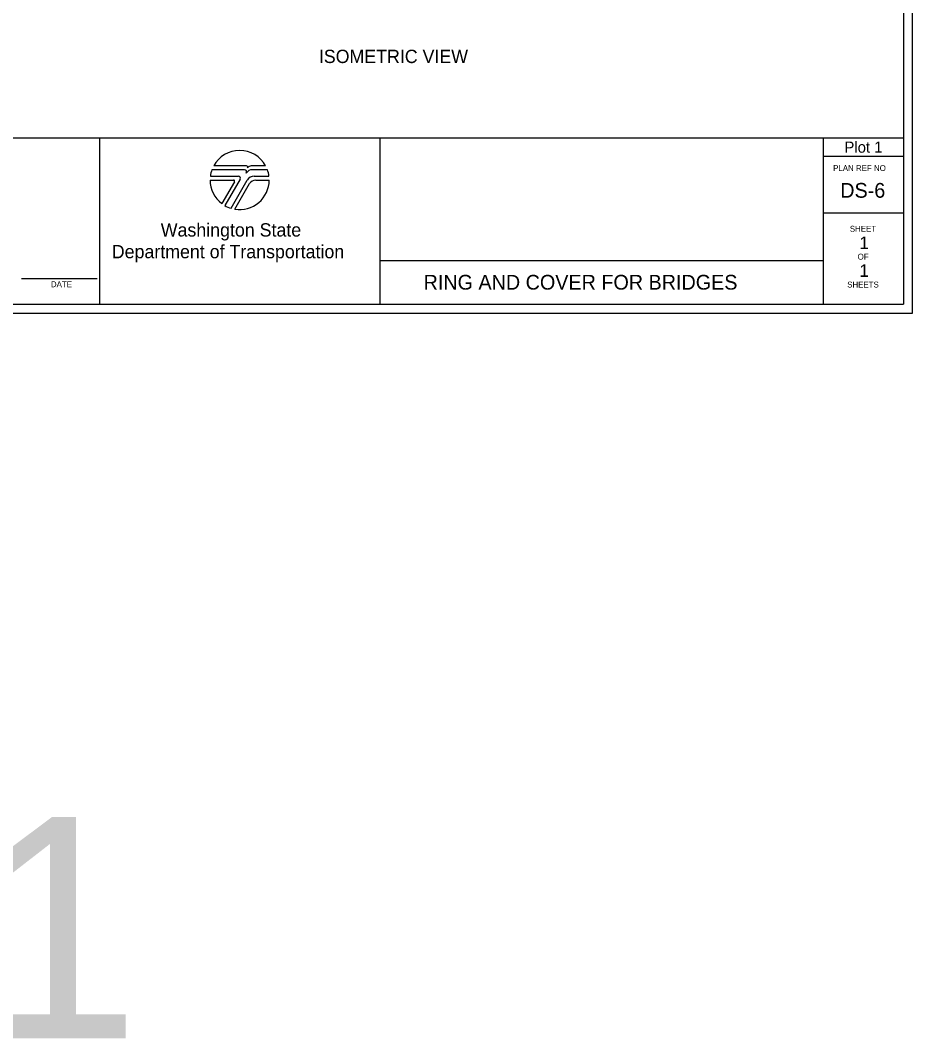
# Model space of a CAD drawing. Extents: x 99988 to 100172, y 99995 to 100047.
# Drawn here: x 100009.77 to 100015.81, y 99995.01 to 100001.92 of the extents above; entities that cross this region are included whole.
import ezdxf

# ---------------------------------------------------------------- set-up
doc = ezdxf.new("R2010")
doc.units = 0
for name, color, linetype in [('Level 10', 7, 'Continuous'), ('SH_GI_PlotLimits', 7, 'Continuous'), ('SH_GI_SheetBorder', 7, 'Continuous'), ('SH_GI_SheetLocationText', 7, 'Continuous'), ('SH_GI_SheetTextInCells', 7, 'Continuous'), ('SH_GI_TitleBlockText', 7, 'Continuous'), ('SH_GI_WSDOTLogo', 7, 'Continuous')]:
    doc.layers.add(name, color=color, linetype=linetype)

msp = doc.modelspace()

# ---------------------------------------------------------------- linework, layer by layer
at = {"layer": 'SH_GI_PlotLimits'}
msp.add_lwpolyline([(99999.3125, 99999.9375), (100015.8125, 99999.9375), (100015.8125, 100010.4375), (99999.3125, 100010.4375)], close=True, dxfattribs=at)
at = {"layer": 'SH_GI_SheetBorder'}
for p, q in [((100015.75, 100010.375), (100015.75, 100000)), ((100000, 100001.1259), (100015.75, 100001.1259)), ((100010.3089, 100001.1259), (100010.3089, 100000)), ((100012.2055, 100001.1259), (100012.2055, 100000)), ((100015.2079, 100001.1259), (100015.2079, 100000)), ((100015.2079, 100001.0008), (100015.75, 100001.0008)), ((100015.2079, 100000.6176), (100015.75, 100000.6176)), ((100012.2055, 100000.2955), (100015.2079, 100000.2955)), ((100009.7797, 100000.1733), (100010.2914, 100000.1733)), ((100000, 100000), (100015.75, 100000))]:
    msp.add_line(p, q, dxfattribs=at)
at = {"layer": 'SH_GI_WSDOTLogo'}
for p, q in [((100011.2894, 100000.9094), (100011.0697, 100000.9094)), ((100011.303, 100000.9354), (100011.0815, 100000.9354)), ((100011.433, 100000.9354), (100011.3351, 100000.9354)), ((100011.343, 100000.9094), (100011.3429, 100000.9094)), ((100011.4448, 100000.9094), (100011.343, 100000.9094)), ((100011.0572, 100000.84), (100011.2148, 100000.84)), ((100011.059, 100000.8661), (100011.2496, 100000.8661)), ((100011.222, 100000.8277), (100011.1364, 100000.6807)), ((100011.261, 100000.8464), (100011.1567, 100000.6672)), ((100011.1989, 100000.6487), (100011.3089, 100000.839)), ((100011.2244, 100000.6428), (100011.3242, 100000.8156)), ((100011.3558, 100000.8661), (100011.4555, 100000.8661)), ((100011.3655, 100000.8394), (100011.4572, 100000.8394))]:
    msp.add_line(p, q, dxfattribs=at)
for centre, radius, start, end in [((100011.2572, 100000.84), 0.2, 28.47865, 151.53204), ((100011.2572, 100000.84), 0.2, 159.69598, 172.50569), ((100011.2894, 100000.8946), 0.0148, 327.8418, 89.99855), ((100011.3429, 100000.861), 0.0484, 89.99529, 147.82376), ((100011.303, 100000.9263), 0.00903, 329.87418, 90.00328), ((100011.3352, 100000.9066), 0.0287, 90.00721, 148.16763), ((100011.2572, 100000.84), 0.2, 7.49431, 20.29406), ((100011.2572, 100000.84), 0.2, 179.99864, 232.84327), ((100011.2149, 100000.8318), 0.0082, 329.74356, 90), ((100011.2572, 100000.84), 0.2, 260.54554, 359.80857), ((100011.2497, 100000.853), 0.0131, 329.76834, 90), ((100011.3558, 100000.8119), 0.0542, 90, 149.99738), ((100011.3654, 100000.7918), 0.0476, 90, 150.05432), ((100011.2572, 100000.84), 0.2, 239.79292, 253.0448)]:
    msp.add_arc(centre, radius, start, end, dxfattribs=at)

# ---------------------------------------------------------------- texts
at = {"layer": 'Level 10'}
msp.add_text('ISOMETRIC VIEW', height=0.09, dxfattribs=at).set_placement((100011.7934, 100001.6322))
at = {"layer": 'SH_GI_SheetBorder'}
msp.add_text('PLAN REF NO', height=0.040032, dxfattribs=at).set_placement((100015.2747, 100000.9008))
at = {"layer": 'SH_GI_SheetLocationText'}
for height, p in [(0.075, (100015.3518, 100001.025)), (1.5, (100005.4547, 99995.0267))]:
    msp.add_text('Plot 1', height=height, dxfattribs=at).set_placement(p)
at = {"layer": 'SH_GI_SheetTextInCells'}
for s, height, p in [('Washington State', 0.090072, (100010.7229, 100000.4571)), ('SHEET', 0.04003, (100015.3877, 100000.4896)), ('Department of Transportation', 0.090072, (100010.3916, 100000.3101)), ('OF', 0.04003, (100015.4406, 100000.3008)), ('DATE', 0.04003, (100009.9794, 100000.1141)), ('SHEETS', 0.04003, (100015.3698, 100000.112))]:
    msp.add_text(s, height=height, dxfattribs=at).set_placement(p)
at = {"layer": 'SH_GI_TitleBlockText'}
for s, height, p in [('DS-6', 0.1, (100015.3229, 100000.72)), ('1', 0.085, (100015.453, 100000.3723)), ('1', 0.085, (100015.453, 100000.1843)), ('RING AND COVER FOR BRIDGES', 0.1, (100012.5022, 100000.0977))]:
    msp.add_text(s, height=height, dxfattribs=at).set_placement(p)

doc.saveas('drawing.dxf')
